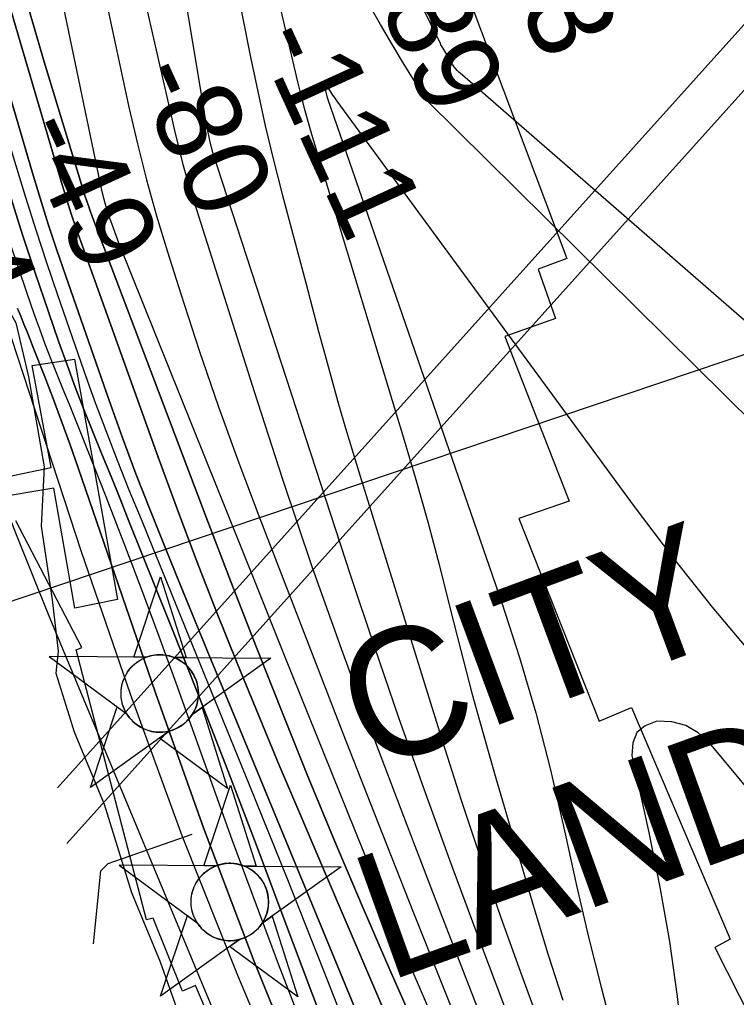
# Model space of a CAD drawing. Extents: x 3625074 to 3663148, y 511451 to 537151.
# Drawn here: x 3658358 to 3658924, y 517442 to 518213 of the extents above; entities that cross this region are included whole.
import ezdxf

# ---------------------------------------------------------------- set-up
doc = ezdxf.new("R2010")
doc.units = 0
for name, color, linetype in [('V-CHAN-DOCK', 7, 'Continuous'), ('V-CHAN-NAID', 7, 'Continuous'), ('V-RIVR-EDGE', 7, 'Continuous'), ('V-RIVR-RANG', 7, 'Continuous'), ('V-RRAP-RVMT', 7, 'Continuous'), ('V-TOPO-DPTH', 7, 'Continuous'), ('V-TOPO-MAJR', 7, 'Continuous'), ('V-TOPO-MINR', 7, 'Continuous'), ('V-TOPO-WATR', 7, 'Continuous'), ('V-UTIL-LINE', 7, 'Continuous')]:
    doc.layers.add(name, color=color, linetype=linetype)

msp = doc.modelspace()

# ---------------------------------------------------------------- linework, layer by layer
at = {"layer": 'V-CHAN-DOCK'}
msp.add_lwpolyline([(3658313.18, 517845.28), (3658332.09, 517849.57), (3658382.59, 517860.1), (3658367.65, 517940.63), (3658401.08, 517945.59), (3658435.08, 517756.07), (3658401.27, 517749.15), (3658384.77, 517843.71), (3658334.31, 517835.34), (3658314.51, 517832.91), (3658313.18, 517845.28)], dxfattribs=at)
at = {"layer": 'V-CHAN-NAID'}
for points in [[(3658457.4, 517710.4), (3658447.82, 517710.46), (3658468.94, 517773.95), (3658489.17, 517710.17), (3658479.58, 517710.24), (3658478, 517710.82), (3658475.91, 517711.44), (3658473.87, 517711.89), (3658471.83, 517712.2), (3658470.66, 517712.31), (3658469.13, 517712.39), (3658467.41, 517712.39), (3658466.04, 517712.32), (3658464.13, 517712.12), (3658462.77, 517711.9), (3658460.98, 517711.52), (3658459.45, 517711.1), (3658458.42, 517710.76)], [(3658457.4, 517710.4), (3658380.91, 517710.94), (3658442.48, 517665.54), (3658441.36, 517667.45), (3658440.55, 517669.08), (3658439.73, 517671.04), (3658439.03, 517673.1), (3658438.67, 517674.42), (3658438.31, 517676.05), (3658438.06, 517677.49), (3658437.88, 517679.09), (3658437.77, 517680.83), (3658437.75, 517682.41), (3658437.86, 517684.48), (3658438.04, 517686.1), (3658438.44, 517688.3), (3658438.92, 517690.23), (3658439.52, 517692.11), (3658440.18, 517693.79), (3658440.9, 517695.38), (3658441.72, 517696.91), (3658442.78, 517698.65), (3658443.81, 517700.12), (3658444.81, 517701.39), (3658445.81, 517702.54), (3658447.12, 517703.87), (3658448.17, 517704.84), (3658449.89, 517706.23), (3658451.1, 517707.11), (3658452.79, 517708.17), (3658454.52, 517709.12), (3658455.96, 517709.8)], [(3658479.58, 517710.24), (3658556.07, 517709.7), (3658493.87, 517665.17), (3658494.78, 517666.66), (3658495.76, 517668.51), (3658496.47, 517670.1), (3658497.21, 517672.05), (3658497.76, 517673.84), (3658498.15, 517675.47), (3658498.52, 517677.48), (3658498.7, 517679.06), (3658498.83, 517681.26), (3658498.79, 517683.33), (3658498.61, 517685.54), (3658498.34, 517687.3), (3658497.85, 517689.54), (3658497.21, 517691.67), (3658496.46, 517693.66), (3658495.81, 517695.1), (3658494.81, 517697.02), (3658493.74, 517698.74), (3658492.53, 517700.44), (3658491.27, 517701.98), (3658490, 517703.35), (3658488.36, 517704.88), (3658486.62, 517706.29), (3658484.94, 517707.47), (3658483.05, 517708.6), (3658481.58, 517709.36)], [(3658475.84, 517652.27), (3658413.63, 517607.75), (3658434.76, 517671.23), (3658442.48, 517665.54), (3658443.11, 517664.58), (3658444.5, 517662.72), (3658445.71, 517661.3), (3658447.17, 517659.8), (3658448.56, 517658.55), (3658450.02, 517657.39), (3658451.42, 517656.4), (3658453.1, 517655.37), (3658454.81, 517654.46), (3658456.6, 517653.65), (3658458.05, 517653.09), (3658459.68, 517652.56), (3658461.9, 517652), (3658463.44, 517651.71), (3658465.46, 517651.45), (3658467, 517651.35), (3658468.86, 517651.33), (3658470.55, 517651.4), (3658472.26, 517651.58), (3658474.16, 517651.89)], [(3658493.87, 517665.17), (3658501.66, 517670.76), (3658521.89, 517606.98), (3658468.04, 517646.69), (3658475.84, 517652.27), (3658477.5, 517652.74), (3658479.12, 517653.3), (3658481.27, 517654.22), (3658483.01, 517655.1), (3658484.87, 517656.22), (3658486.61, 517657.43), (3658488.17, 517658.67), (3658489.45, 517659.84), (3658490.84, 517661.26), (3658492.04, 517662.66), (3658493.16, 517664.14)], [(3658512.73, 517545.96), (3658503.14, 517546.03), (3658524.27, 517609.51), (3658544.49, 517545.74), (3658534.91, 517545.8), (3658533.33, 517546.38), (3658531.23, 517547), (3658529.19, 517547.45), (3658527.16, 517547.76), (3658525.99, 517547.88), (3658524.46, 517547.96), (3658522.73, 517547.95), (3658521.37, 517547.88), (3658519.46, 517547.68), (3658518.09, 517547.46), (3658516.31, 517547.08), (3658514.78, 517546.66), (3658513.75, 517546.33)], [(3658512.73, 517545.96), (3658436.24, 517546.5), (3658497.8, 517501.1), (3658496.69, 517503.01), (3658495.88, 517504.64), (3658495.06, 517506.61), (3658494.36, 517508.66), (3658494, 517509.99), (3658493.63, 517511.61), (3658493.39, 517513.06), (3658493.2, 517514.66), (3658493.09, 517516.39), (3658493.08, 517517.97), (3658493.19, 517520.05), (3658493.37, 517521.66), (3658493.76, 517523.87), (3658494.24, 517525.79), (3658494.85, 517527.68), (3658495.5, 517529.36), (3658496.23, 517530.94), (3658497.04, 517532.48), (3658498.1, 517534.22), (3658499.14, 517535.69), (3658500.14, 517536.96), (3658501.14, 517538.1), (3658502.45, 517539.44), (3658503.5, 517540.4), (3658505.21, 517541.8), (3658506.43, 517542.67), (3658508.11, 517543.74), (3658509.84, 517544.68), (3658511.29, 517545.37)], [(3658534.91, 517545.8), (3658611.4, 517545.26), (3658549.2, 517500.74), (3658550.11, 517502.23), (3658551.08, 517504.08), (3658551.8, 517505.66), (3658552.54, 517507.61), (3658553.08, 517509.4), (3658553.48, 517511.04), (3658553.84, 517513.05), (3658554.03, 517514.62), (3658554.15, 517516.83), (3658554.12, 517518.89), (3658553.93, 517521.11), (3658553.67, 517522.87), (3658553.18, 517525.1), (3658552.54, 517527.24), (3658551.79, 517529.22), (3658551.14, 517530.67), (3658550.13, 517532.58), (3658549.07, 517534.3), (3658547.86, 517536.01), (3658546.6, 517537.54), (3658545.32, 517538.91), (3658543.69, 517540.44), (3658541.95, 517541.85), (3658540.27, 517543.03), (3658538.38, 517544.16), (3658536.91, 517544.92)], [(3658531.16, 517487.83), (3658468.96, 517443.31), (3658490.09, 517506.79), (3658497.8, 517501.1), (3658498.44, 517500.14), (3658499.82, 517498.28), (3658501.04, 517496.86), (3658502.5, 517495.36), (3658503.89, 517494.11), (3658505.34, 517492.96), (3658506.75, 517491.97), (3658508.43, 517490.93), (3658510.14, 517490.02), (3658511.93, 517489.21), (3658513.38, 517488.65), (3658515, 517488.12), (3658517.23, 517487.56), (3658518.76, 517487.27), (3658520.79, 517487.02), (3658522.32, 517486.91), (3658524.19, 517486.89), (3658525.87, 517486.97), (3658527.58, 517487.15), (3658529.49, 517487.46)], [(3658549.2, 517500.74), (3658556.99, 517506.32), (3658577.21, 517442.54), (3658523.37, 517482.25), (3658531.16, 517487.83), (3658532.83, 517488.31), (3658534.44, 517488.87), (3658536.6, 517489.78), (3658538.33, 517490.67), (3658540.2, 517491.78), (3658541.94, 517492.99), (3658543.49, 517494.24), (3658544.78, 517495.41), (3658546.16, 517496.83), (3658547.37, 517498.23), (3658548.49, 517499.7)]]:
    msp.add_lwpolyline(points, close=True, dxfattribs=at)
for centre in [(3658468.29, 517681.86), (3658523.62, 517517.43)]:
    msp.add_circle(centre, 30.54, dxfattribs=at)
at = {"layer": 'V-RIVR-EDGE'}
msp.add_lwpolyline([(3658312.16, 518038.52), (3658333.1, 518012.65), (3658354.62, 517974.18), (3658364.72, 517931.53), (3658377.15, 517860.66), (3658374.63, 517813.84), (3658383.5, 517755.59), (3658388.2, 517715.35), (3658386.35, 517697.95), (3658400.65, 517651.69), (3658424.52, 517594.6), (3658445.96, 517524.91), (3658468.64, 517470.22), (3658496.06, 517393.31), (3658522.93, 517335.01), (3658533.6, 517277.36), (3658544.88, 517229.9), (3658569.91, 517154.8), (3658571.15, 517153.78)], dxfattribs=at)
at = {"layer": 'V-RIVR-RANG'}
msp.add_line((3658175.91, 517695.71), (3659066.84, 517995.46), dxfattribs=at)
at = {"layer": 'V-RRAP-RVMT'}
for p, q in [((3658713.78, 518225.95), (3658789.73, 518024.81)), ((3658789.73, 518024.81), (3658766.93, 518016.47)), ((3658766.93, 518016.47), (3658780.58, 517977.47)), ((3658780.58, 517977.47), (3658740.7, 517963.32)), ((3658740.7, 517963.32), (3658791.52, 517833.4)), ((3658791.52, 517833.4), (3658751.61, 517819.84)), ((3658406.7, 517718.07), (3658354.79, 517818.11)), ((3658751.61, 517819.84), (3658815.16, 517660.04)), ((3658402.39, 517716.35), (3658406.7, 517718.07)), ((3658457.84, 517503.32), (3658402.39, 517716.35)), ((3658815.16, 517660.04), (3658840.71, 517670.88)), ((3658840.71, 517670.88), (3658918.42, 517488.03)), ((3658463.2, 517504.79), (3658457.84, 517503.32)), ((3658486.19, 517447.06), (3658463.2, 517504.79)), ((3658918.42, 517488.03), (3658906.53, 517481.6)), ((3658906.53, 517481.6), (3658941.88, 517411.59)), ((3658496.48, 517451.54), (3658486.19, 517447.06)), ((3658517.81, 517402.02), (3658496.48, 517451.54))]:
    msp.add_line(p, q, dxfattribs=at)
at = {"layer": 'V-TOPO-DPTH'}
for points in [[(3658111.34, 519234.6), (3658193.47, 518833.33), (3658221.89, 518703.02), (3658252.51, 518573.26), (3658286.44, 518444.33), (3658322.58, 518315.95), (3658391.64, 518082.13), (3658395, 518071.11), (3658398.48, 518060.13), (3658402.16, 518049.21), (3658405.95, 518038.33), (3658466.98, 517868.28), (3658481.96, 517827.42), (3658497.28, 517786.7), (3658513.15, 517746.17), (3658529.37, 517705.79), (3658545.96, 517665.55), (3658562.68, 517625.37), (3658579.6, 517585.27), (3658596.65, 517545.22), (3658763.64, 517155.71)], [(3658763.64, 517155.71), (3658596.65, 517545.22), (3658579.6, 517585.27), (3658562.68, 517625.37), (3658545.96, 517665.55), (3658529.37, 517705.79), (3658513.15, 517746.17), (3658497.28, 517786.7), (3658481.96, 517827.42), (3658466.98, 517868.28), (3658405.95, 518038.33), (3658402.16, 518049.21), (3658398.48, 518060.13), (3658395, 518071.11), (3658391.64, 518082.13), (3658322.58, 518315.95), (3658286.44, 518444.33), (3658252.51, 518573.26), (3658221.89, 518703.02), (3658193.47, 518833.33), (3658111.34, 519234.6)], [(3657890.61, 519160.02), (3657989.56, 518864.66), (3658037.58, 518721.47), (3658085.67, 518578.31), (3658133.86, 518435.18), (3658182.13, 518292.07), (3658261.43, 518057.2), (3658270.24, 518031.6), (3658279.24, 518006.06), (3658288.54, 517980.63), (3658298.03, 517955.28), (3658328.92, 517874.2), (3658354.49, 517808.56), (3658380.72, 517743.19), (3658407.92, 517678.21), (3658626.28, 517154.33), (3658677.21, 517154.85)], [(3658147.01, 518845.07), (3658367.61, 518093.18), (3658373.85, 518072.48), (3658380.31, 518051.86), (3658387.09, 518031.34), (3658394.08, 518010.88), (3658428.1, 517913.81), (3658438.67, 517884.37), (3658449.55, 517855.05), (3658460.88, 517825.9), (3658472.51, 517796.86), (3658484.39, 517767.92), (3658496.28, 517738.99), (3658508.2, 517710.06), (3658520.14, 517681.14), (3658640.2, 517390.68), (3658662.02, 517337.63), (3658683.7, 517284.52), (3658705.2, 517231.34), (3658726.56, 517178.11), (3658733.36, 517161.07), (3658735.69, 517155.43)], [(3658735.69, 517155.43), (3658733.36, 517161.07), (3658726.56, 517178.11), (3658705.2, 517231.34), (3658683.7, 517284.52), (3658662.02, 517337.63), (3658640.2, 517390.68), (3658520.14, 517681.14), (3658508.2, 517710.06), (3658496.28, 517738.99), (3658484.39, 517767.92), (3658472.51, 517796.86), (3658460.88, 517825.9), (3658449.55, 517855.05), (3658438.67, 517884.37), (3658428.1, 517913.81), (3658394.08, 518010.88), (3658387.09, 518031.34), (3658380.31, 518051.86), (3658373.85, 518072.48), (3658367.61, 518093.18), (3658147.01, 518845.07)], [(3658621.92, 517358.36), (3658588.25, 517445.78), (3658566.37, 517504.5), (3658544.38, 517562.88), (3658522.1, 517621.14), (3658499.38, 517679.24), (3658476.38, 517737.22), (3658444.04, 517817.85), (3658436.97, 517835.43), (3658429.87, 517853), (3658422.73, 517870.55), (3658415.57, 517888.1), (3658408.52, 517905.69), (3658401.68, 517923.35), (3658395.11, 517941.12), (3658388.74, 517958.96), (3658380.43, 517982.87), (3658370.22, 518012.77), (3658360.26, 518042.76), (3658350.67, 518072.87), (3658341.31, 518103.05), (3658206.15, 518548.6)], [(3658206.15, 518548.6), (3658341.31, 518103.05), (3658350.67, 518072.87), (3658360.26, 518042.76), (3658370.22, 518012.77), (3658380.43, 517982.87), (3658388.74, 517958.96), (3658395.11, 517941.12), (3658401.68, 517923.35), (3658408.52, 517905.69), (3658415.57, 517888.1), (3658422.73, 517870.55), (3658429.87, 517853), (3658436.97, 517835.43), (3658444.04, 517817.85), (3658476.38, 517737.22), (3658499.38, 517679.24), (3658522.1, 517621.14), (3658544.38, 517562.88), (3658566.37, 517504.5), (3658588.25, 517445.78), (3658621.92, 517358.36)], [(3658360.5, 518236.87), (3658377.14, 518179.87), (3658409.53, 518073.89), (3658410.74, 518070.07), (3658412, 518066.28), (3658413.33, 518062.51), (3658414.71, 518058.76), (3658504.95, 517820.88), (3658524.66, 517769.48), (3658544.61, 517718.17), (3658564.94, 517667.01), (3658585.51, 517615.95), (3658606.54, 517565.08), (3658627.95, 517514.37), (3658649.91, 517463.89), (3658672.24, 517413.58), (3658788.27, 517155.96)], [(3658788.27, 517155.96), (3658672.24, 517413.58), (3658649.91, 517463.89), (3658627.95, 517514.37), (3658606.54, 517565.08), (3658585.51, 517615.95), (3658564.94, 517667.01), (3658544.61, 517718.17), (3658524.66, 517769.48), (3658504.95, 517820.88), (3658414.71, 518058.76), (3658413.33, 518062.51), (3658412, 518066.28), (3658410.74, 518070.07), (3658409.53, 518073.89), (3658377.14, 518179.87), (3658360.5, 518236.87)], [(3658585.33, 517365.96), (3658542.76, 517470.47), (3658502.89, 517576.04), (3658464.83, 517682.32), (3658403.83, 517859.81), (3658397.51, 517877.84), (3658391.04, 517895.8), (3658384.35, 517913.69), (3658377.52, 517931.52), (3658368.43, 517954.79), (3658366.01, 517960.94), (3658363.57, 517967.09), (3658361.1, 517973.22), (3658358.6, 517979.35), (3658356.15, 517985.49)], [(3658585.33, 517365.96), (3658542.76, 517470.47), (3658502.89, 517576.04), (3658464.83, 517682.32), (3658403.83, 517859.81), (3658397.51, 517877.84), (3658391.04, 517895.8), (3658384.35, 517913.69), (3658377.52, 517931.52), (3658368.43, 517954.79), (3658366.01, 517960.94), (3658363.57, 517967.09), (3658361.1, 517973.22), (3658358.6, 517979.35), (3658356.15, 517985.49)]]:
    msp.add_lwpolyline(points, dxfattribs=at)
at = {"layer": 'V-TOPO-MAJR'}
for points in [[(3658315.61, 518590.14), (3658421.26, 518083.69), (3658422.62, 518077.69), (3658424.11, 518071.72), (3658425.81, 518065.82), (3658427.65, 518059.94), (3658429.64, 518054.12), (3658431.7, 518048.32), (3658433.87, 518042.56), (3658436.11, 518036.83), (3658542.49, 517771.93), (3658567.12, 517710.66), (3658591.77, 517649.4), (3658616.47, 517588.15), (3658641.19, 517526.92), (3658666.47, 517465.92), (3658692.46, 517405.24), (3658719.52, 517345.03), (3658747.29, 517285.13), (3658808.47, 517156.16)], [(3659126.08, 517707.75), (3658679.49, 518149.13), (3658669.94, 518164.04), (3658660.56, 518179.05), (3658651.44, 518194.22), (3658642.49, 518209.5), (3658552.71, 518365.86)], [(3658538.91, 518327.44), (3658577.06, 518164.07), (3658579.58, 518153.72), (3658582.24, 518143.41), (3658585.1, 518133.15), (3658588.09, 518122.93), (3658660.56, 517884.12), (3658670.4, 517850.68), (3658679.88, 517817.14), (3658688.81, 517783.46), (3658697.37, 517749.67), (3658705.88, 517715.86), (3658714.7, 517682.14), (3658723.99, 517648.55), (3658733.59, 517615.04), (3658763.53, 517513.18), (3658774.71, 517476.48), (3658786.37, 517439.94)]]:
    msp.add_lwpolyline(points, dxfattribs=at)
at = {"layer": 'V-TOPO-MINR'}
for points in [[(3658111.34, 519234.6), (3658193.47, 518833.33), (3658221.89, 518703.02), (3658252.51, 518573.26), (3658286.44, 518444.33), (3658322.58, 518315.95), (3658391.64, 518082.13), (3658395, 518071.11), (3658398.48, 518060.13), (3658402.16, 518049.21), (3658405.95, 518038.33), (3658466.98, 517868.28), (3658481.96, 517827.42), (3658497.28, 517786.7), (3658513.15, 517746.17), (3658529.37, 517705.79), (3658545.96, 517665.55), (3658562.68, 517625.37), (3658579.6, 517585.27), (3658596.65, 517545.22), (3658763.64, 517155.71)], [(3657986.95, 519175.12), (3658322.31, 518049.69), (3658323.37, 518046.17), (3658324.43, 518042.64), (3658325.52, 518039.13), (3658326.61, 518035.61), (3658328.38, 518030), (3658328.6, 518029.29), (3658329.65, 518026.21), (3658330.46, 518024.14), (3658332.19, 518019.6), (3658332.97, 518017.3), (3658406.37, 517793.81), (3658445.02, 517681.51), (3658485.78, 517570.01), (3658529.67, 517459.71), (3658575.67, 517350.22), (3658661.09, 517154.68)], [(3657890.61, 519160.02), (3657989.56, 518864.66), (3658037.58, 518721.47), (3658085.67, 518578.31), (3658133.86, 518435.18), (3658182.13, 518292.07), (3658261.43, 518057.2), (3658270.24, 518031.6), (3658279.24, 518006.06), (3658288.54, 517980.63), (3658298.03, 517955.28), (3658328.92, 517874.2), (3658354.49, 517808.56), (3658380.72, 517743.19), (3658407.92, 517678.21), (3658626.28, 517154.33)], [(3658049.35, 519126.11), (3658354.54, 518099.03), (3658362.42, 518073.19), (3658370.53, 518047.42), (3658378.99, 518021.76), (3658387.7, 517996.18), (3658408.49, 517936.41), (3658416.93, 517912.76), (3658425.63, 517889.2), (3658434.71, 517865.79), (3658444.04, 517842.48), (3658453.56, 517819.23), (3658463.06, 517795.98), (3658472.55, 517772.72), (3658482.02, 517749.46), (3658539.11, 517609.18), (3658568.5, 517536.4), (3658597.63, 517463.51), (3658626.36, 517390.46), (3658654.83, 517317.31), (3658655.64, 517315.22), (3658684.28, 517243.37), (3658713.96, 517171.95), (3658721.31, 517155.29)], [(3658147.01, 518845.07), (3658367.61, 518093.18), (3658373.85, 518072.48), (3658380.31, 518051.86), (3658387.09, 518031.34), (3658394.08, 518010.88), (3658428.1, 517913.81), (3658438.67, 517884.37), (3658449.55, 517855.05), (3658460.88, 517825.9), (3658472.51, 517796.86), (3658484.39, 517767.92), (3658496.28, 517738.99), (3658508.2, 517710.06), (3658520.14, 517681.14), (3658640.2, 517390.68), (3658662.02, 517337.63), (3658683.7, 517284.52), (3658705.2, 517231.34), (3658726.56, 517178.11), (3658733.36, 517161.07), (3658735.69, 517155.43)], [(3658421.51, 518630.88), (3658503.02, 518141.74), (3658503.63, 518138.19), (3658504.25, 518134.65), (3658504.89, 518131.11), (3658505.55, 518127.58), (3658505.93, 518125.59), (3658506.44, 518123.06), (3658506.98, 518120.52), (3658507.56, 518118), (3658508.16, 518115.49), (3658509.32, 518110.9), (3658509.7, 518109.62), (3658618.67, 517775.82), (3658637.49, 517719.25), (3658656.75, 517662.82), (3658676.65, 517606.62), (3658696.98, 517550.57), (3658717.76, 517494.68), (3658738.72, 517438.85), (3658759.92, 517383.12), (3658781.3, 517327.46), (3658845.8, 517160.67), (3658847.46, 517156.55)], [(3659545.94, 517440.57), (3658707.28, 518169.45), (3658704.5, 518171.87), (3658703.19, 518173.18), (3658700.82, 518176), (3658699.76, 518177.51), (3658698.76, 518179.06), (3658691.63, 518190.97), (3658690.22, 518193.48), (3658689.79, 518194.34), (3658504.54, 518567.99)], [(3658206.15, 518548.6), (3658341.31, 518103.05), (3658350.67, 518072.87), (3658360.26, 518042.76), (3658370.22, 518012.77), (3658380.43, 517982.87), (3658388.74, 517958.96), (3658395.11, 517941.12), (3658401.68, 517923.35), (3658408.52, 517905.69), (3658415.57, 517888.1), (3658422.73, 517870.55), (3658429.87, 517853), (3658436.97, 517835.43), (3658444.04, 517817.85), (3658476.38, 517737.22), (3658499.38, 517679.24), (3658522.1, 517621.14), (3658544.38, 517562.88), (3658566.37, 517504.5), (3658588.25, 517445.78), (3658621.92, 517358.36)], [(3658478.4, 518493.85), (3658539.95, 518183.65), (3658545.61, 518156.48), (3658551.61, 518129.4), (3658558.12, 518102.43), (3658564.97, 518075.54), (3658583.5, 518005.61), (3658588.6, 517986.49), (3658593.73, 517967.37), (3658598.91, 517948.27), (3658604.14, 517929.17), (3658609.48, 517910.12), (3658614.95, 517891.1), (3658620.61, 517872.13), (3658626.4, 517853.2), (3658691.47, 517644.12), (3658706.33, 517597.63), (3658721.64, 517551.29), (3658737.65, 517505.19), (3658754.13, 517459.24), (3658771.01, 517413.44)], [(3658404.37, 518328.48), (3658444.01, 518144.19), (3658450.63, 518115.42), (3658457.8, 518086.8), (3658465.79, 518058.4), (3658474.33, 518030.14), (3658484.89, 517996.93), (3658499.53, 517952.32), (3658514.71, 517907.91), (3658530.71, 517863.78), (3658547.25, 517819.84), (3658585.36, 517721.4), (3658612.92, 517650.54), (3658640.63, 517579.73), (3658668.57, 517509.01), (3658696.66, 517438.36), (3658725.71, 517368.12), (3658755.87, 517298.38), (3658787.71, 517229.39), (3658820.67, 517160.9), (3658822.95, 517156.31)], [(3658279.94, 518263.43), (3658336.83, 518078.65), (3658343.22, 518058.31), (3658349.75, 518038.03), (3658356.49, 518017.81), (3658363.39, 517997.64), (3658369, 517981.52), (3658373.29, 517969.48), (3658377.72, 517957.5), (3658382.34, 517945.58), (3658387.09, 517933.72), (3658391.91, 517921.88), (3658396.71, 517910.03), (3658401.46, 517898.17), (3658406.18, 517886.29), (3658425.65, 517837.08), (3658439.91, 517800.52), (3658453.92, 517763.88), (3658467.58, 517727.09), (3658481, 517690.22), (3658525.24, 517566.76), (3658561.75, 517468.55), (3658599.79, 517370.97)], [(3658360.5, 518236.87), (3658377.14, 518179.87), (3658409.53, 518073.89), (3658410.74, 518070.07), (3658412, 518066.28), (3658413.33, 518062.51), (3658414.71, 518058.76), (3658504.95, 517820.88), (3658524.66, 517769.48), (3658544.61, 517718.17), (3658564.94, 517667.01), (3658585.51, 517615.95), (3658606.54, 517565.08), (3658627.95, 517514.37), (3658649.91, 517463.89), (3658672.24, 517413.58), (3658788.27, 517155.96)], [(3658457.74, 518222.65), (3658479.89, 518125.86), (3658483.04, 518112.87), (3658486.39, 518099.93), (3658490.05, 518087.07), (3658493.93, 518074.27), (3658542.71, 517920.04), (3658565.19, 517850.93), (3658588.41, 517782.08), (3658612.75, 517713.61), (3658637.83, 517645.4), (3658663.62, 517577.44), (3658689.61, 517509.56), (3658715.89, 517441.79), (3658742.37, 517374.1), (3658765.21, 517316.09), (3658790.29, 517254.68), (3658816.39, 517193.72), (3658833.49, 517156.41)], [(3658936.8, 517711.72), (3658904.48, 517750), (3658873.37, 517789.29), (3658843.07, 517829.23), (3658608.35, 518149.04), (3658606.64, 518151.4), (3658604.96, 518153.79), (3658603.3, 518156.19), (3658601.67, 518158.62), (3658598.96, 518162.71), (3658598.75, 518162.85), (3658598.55, 518162.88), (3658598.38, 518162.78), (3658598.23, 518162.58), (3658598.13, 518161.68), (3658598.17, 518161.23), (3658598.25, 518160.78), (3658600.31, 518152.6), (3658600.67, 518151.36), (3658600.81, 518150.95), (3658738.24, 517753.44), (3658752.27, 517710.22), (3658765.21, 517666.69), (3658776.49, 517622.71), (3658786.67, 517578.42), (3658788.19, 517571.2), (3658797.16, 517530.38), (3658806.64, 517489.69), (3658816.88, 517449.18), (3658827.62, 517408.8)], [(3658951.77, 517583.43), (3658902.19, 517642.95), (3658893.31, 517650.82), (3658883.58, 517656.64), (3658872.59, 517659.38), (3658860.74, 517660.08), (3658851.52, 517656.43), (3658844.74, 517651), (3658841.62, 517642.88), (3658840.95, 517632.98), (3658854.31, 517572.16), (3658862.95, 517529.25), (3658870.57, 517486.17), (3658876.66, 517442.86), (3658881.74, 517399.39)]]:
    msp.add_lwpolyline(points, dxfattribs=at)
at = {"layer": 'V-TOPO-WATR'}
msp.add_lwpolyline([(3658356.15, 517985.49), (3658358.6, 517979.35), (3658361.1, 517973.22), (3658363.57, 517967.09), (3658366.01, 517960.94), (3658368.43, 517954.79), (3658377.52, 517931.52), (3658384.35, 517913.69), (3658391.04, 517895.8), (3658397.51, 517877.84), (3658403.83, 517859.81), (3658464.83, 517682.32), (3658502.89, 517576.04), (3658542.76, 517470.47), (3658585.33, 517365.96)], dxfattribs=at)
at = {"layer": 'V-UTIL-LINE'}
for p, q in [((3658387.56, 517607.48), (3660280.6, 519710.64)), ((3658394.86, 517563.67), (3660287.9, 519666.82))]:
    msp.add_line(p, q, dxfattribs=at)
msp.add_lwpolyline([(3658416.08, 517484.45), (3658421.73, 517542.08), (3658427.7, 517547.84), (3658493.86, 517571.05)], dxfattribs=at)

# ---------------------------------------------------------------- texts
at = {"layer": 'V-CHAN-NAID'}
for s, rotation, p in [('CITY OF WESTWEGO', 20.36681, (3658634.28, 517619.44)), (' LANDING (101.7) (2)', 19.8263, (3658612.98, 517441.67))]:
    msp.add_text(s, height=100, rotation=rotation, dxfattribs=at).set_placement(p)
at = {"layer": 'V-RIVR-RANG'}
for s, rotation, p in [('-83', 294.52803, (3658718.72, 518295.9)), ('-89', 294.52803, (3658629.06, 518251.49)), ('-111', 294.52803, (3658543.46, 518198.2)), ('-80', 294.52803, (3658446.47, 518169.87)), ('-49', 294.52803, (3658356.26, 518126.67)), ('5.4', 294.24833, (3658262.43, 518092.42))]:
    msp.add_text(s, height=67, rotation=rotation, dxfattribs=at).set_placement(p)

doc.saveas('drawing.dxf')
